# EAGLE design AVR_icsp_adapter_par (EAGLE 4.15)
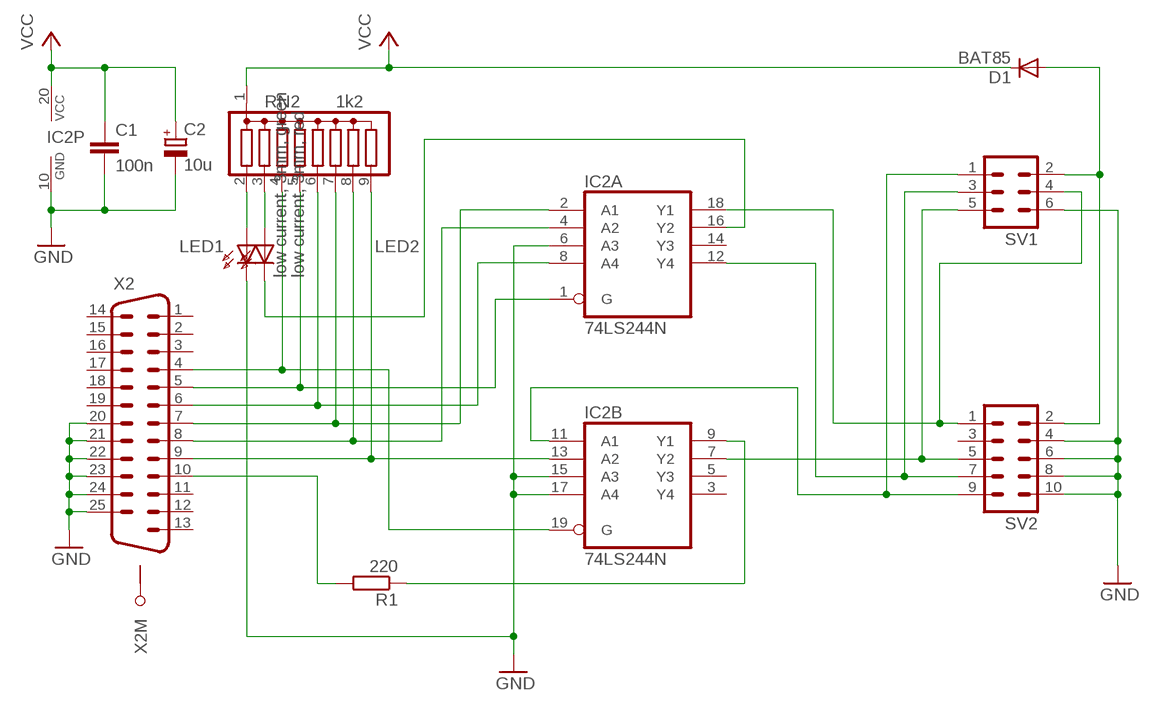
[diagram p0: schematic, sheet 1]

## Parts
C1  100n  C-EU025-025X050  [C025-025X050]
C2  10u  CPOL-EUE2.5-5  [E2,5-5]
D1  BAT85  1N4148  [DO35-10]
IC2  74LS244N  [DIL20]
LED1  low current, 3mm, green  LED3MM  [LED3MM]
LED2  low current, 3mm, red  LED3MM  [LED3MM]
R1  220  R-EU_0309/12  [0309/12]
RN2  1k2  G08R  [SIL9]
SV1  MA03-2  [MA03-2]
SV2  MA05-2  [MA05-2]
X2  M25HP  [M25HP]

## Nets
GND: C1.2 C2.- IC2.6(A:A3) IC2.10(P:GND) IC2.15(B:A3) IC2.17(B:A4) LED1.K(C) SV1.6 SV2.4 SV2.6 SV2.8 SV2.10 X2.20 X2.21 X2.22 X2.23 X2.24 X2.25
N$1: IC2.2(A:A1) RN2.7 X2.7
N$2: IC2.12(A:Y4) SV1.3 SV2.7
N$3: D1.A SV1.2 SV2.2
N$4: IC2.7(B:Y2) SV1.5 SV2.5
N$5: IC2.11(B:A1) SV1.1 SV2.9
N$6: IC2.9(B:Y1) R1.1
N$7: LED2.A RN2.3
N$8: IC2.4(A:A2) RN2.8 X2.8
N$9: IC2.18(A:Y1) SV1.4 SV2.1
N$10: IC2.8(A:A4) RN2.6 X2.6
N$11: IC2.16(A:Y2) LED2.K(C)
N$12: LED1.A RN2.2
N$14: IC2.13(B:A2) RN2.9 X2.9
N$15: IC2.1(A:G) RN2.5 X2.5
N$16: IC2.19(B:G) RN2.4 X2.4
N$17: R1.2 X2.10
VCC: C1.1 C2.+ D1.C IC2.20(P:VCC) RN2.1
Unconnected: IC2.3(B:Y4) IC2.5(B:Y3) IC2.14(A:Y3) SV2.3 X2.1 X2.2 X2.3 X2.11 X2.12 X2.13 X2.14 X2.15 X2.16 X2.17 X2.18 X2.19 X2.G1 X2.G2

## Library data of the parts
C1 = rcl:C-EU: CAPACITOR, European symbol
C2 = rcl:CPOL-EU: POLARIZED CAPACITOR, European symbol
D1 = diode:1N4148: DIODE
IC2 = 74xx-eu:74*244: Octal BUFFER and LINE DRIVER, 3-state
LED1 LED2 = led:LED3MM: LED
R1 = rcl:R-EU_: RESISTOR, European symbol
RN2 = resistor-sil:G08R: SIL RESISTOR
SV1 = con-lstb:MA03-2: PIN HEADER
SV2 = con-lstb:MA05-2: PIN HEADER
X2 = con-subd:M25HP: SUB-D

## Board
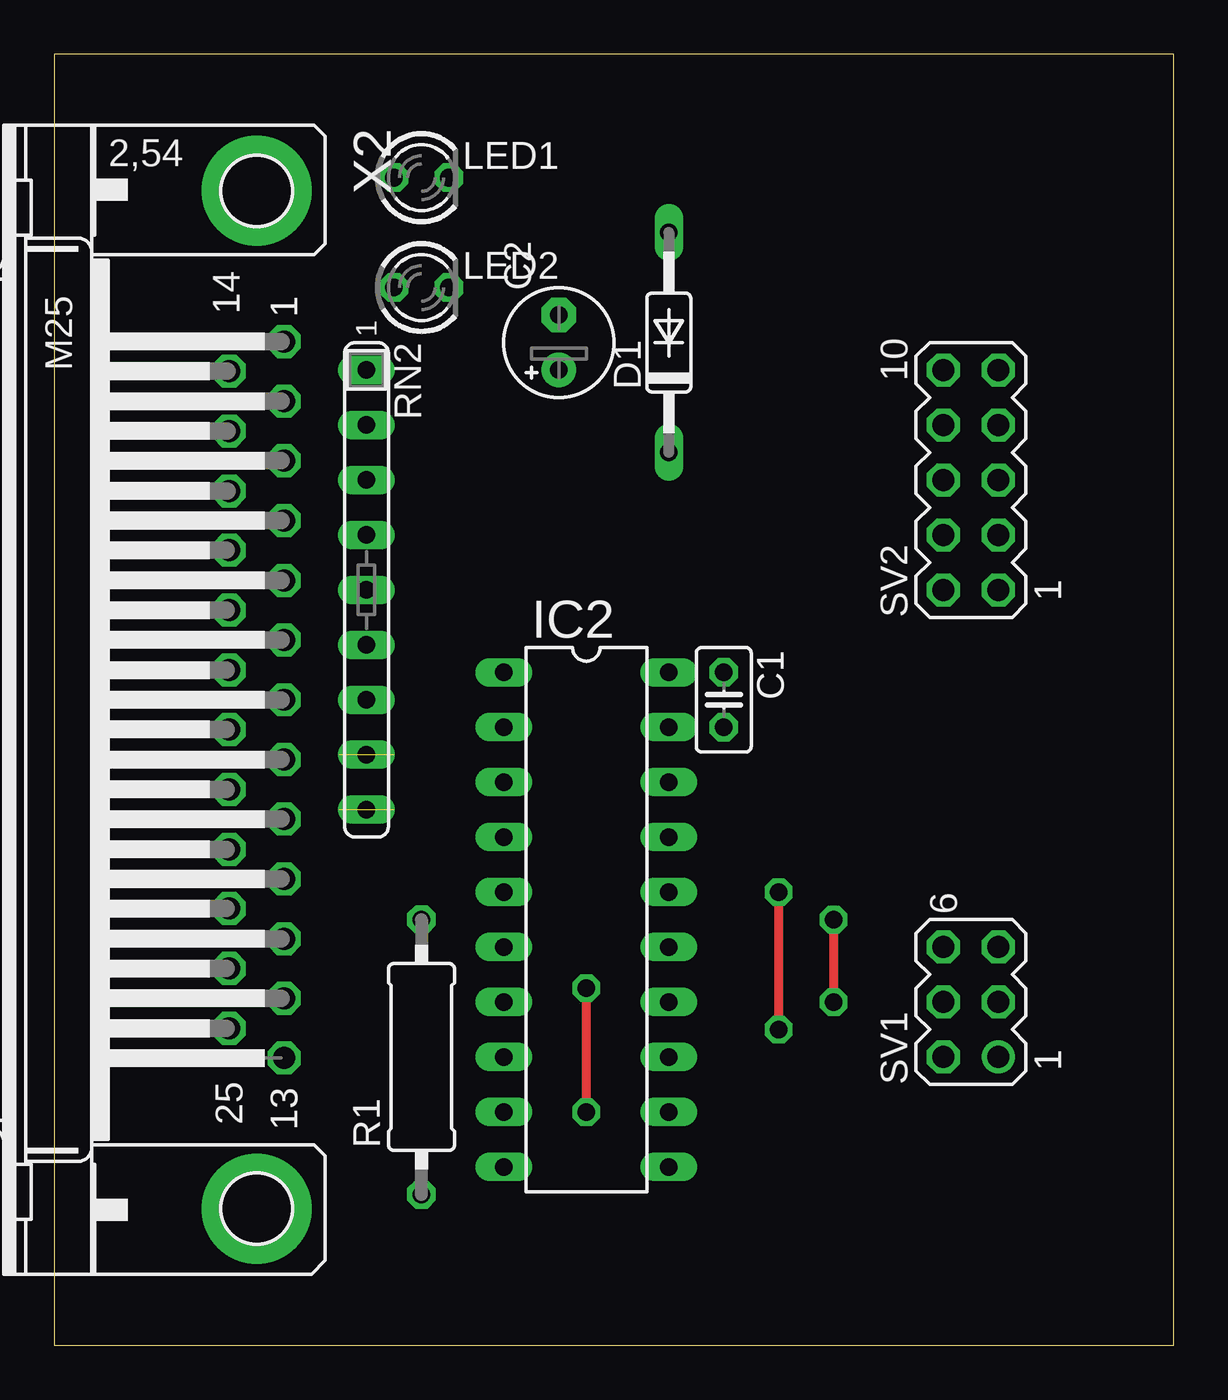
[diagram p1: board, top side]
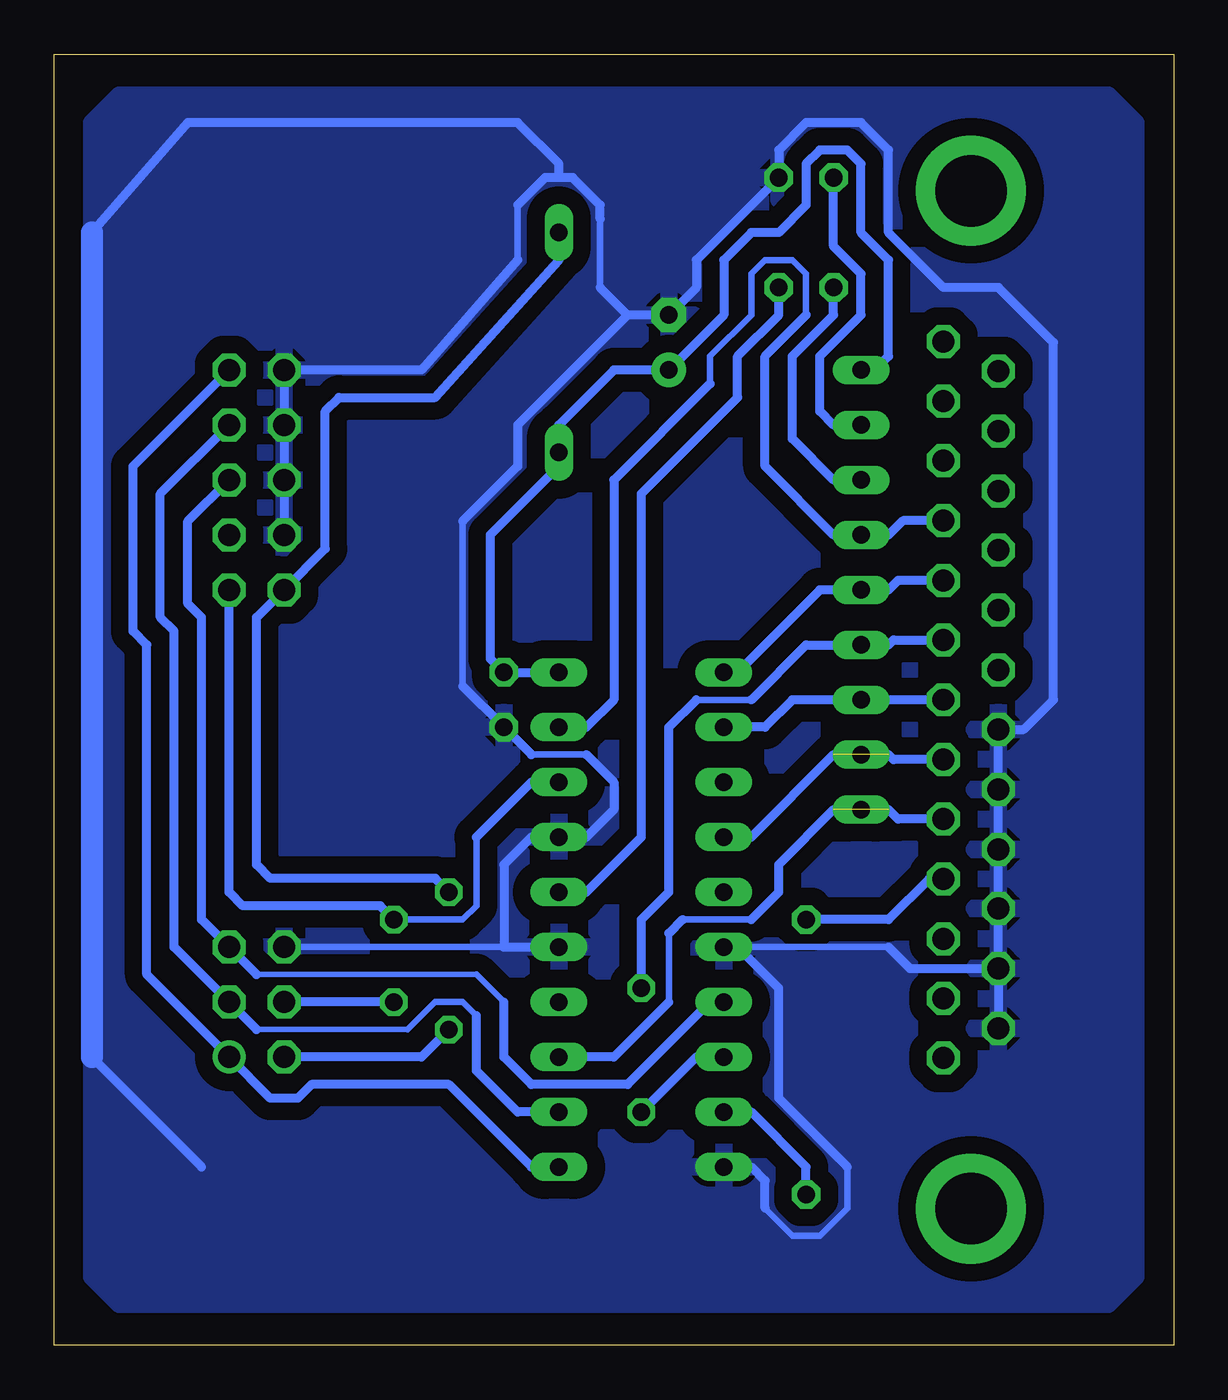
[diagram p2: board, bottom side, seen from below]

Size 51.74 x 59.68 mm. Coordinates in mm from the lower left corner, seen from the top.
Outline: 0,0 51.74,0 51.74,59.68 0,59.68 0,0
Copper layers (1*16): Top 0.035mm / dielectric 1.5mm / Bottom 0.035mm
Design rules "default": minimum track width 10mil, minimum drill 24mil, track to track 8mil, track to pad 8mil, pad to pad 8mil, via to via 8mil, smd to smd 8mil, copper to edge 40mil, drill to drill 8mil, minimum pad ring 10mil, minimum via ring 8mil, stop-mask expansion 4mil, vias tented up to drill 0mil, thermal gap 10mil

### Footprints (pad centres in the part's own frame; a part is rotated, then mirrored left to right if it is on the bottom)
C025-025X050 = drill 0.813 octagon: 1 -1.27,0; 2 1.27,0
E2,5-5 = drill 0.813 pad 1.6 round: + -1.27,0 | drill 0.813 pad 1.6 octagon: - 1.27,0
DO35-10 = drill 0.813 long: A 5.08,0; C -5.08,0
DIL20 = drill 0.813 long: 1 -11.43,-3.81; 2 -8.89,-3.81; 3 -6.35,-3.81; 4 -3.81,-3.81; 5 -1.27,-3.81; 6 1.27,-3.81; 7 3.81,-3.81; 8 6.35,-3.81; 9 8.89,-3.81; 10 11.43,-3.81; 11 11.43,3.81; 12 8.89,3.81; 13 6.35,3.81; 14 3.81,3.81; 15 1.27,3.81; 16 -1.27,3.81; 17 -3.81,3.81; 18 -6.35,3.81; 19 -8.89,3.81; 20 -11.43,3.81
LED3MM = drill 0.813 octagon: A -1.27,0; K 1.27,0
0309/12 = drill 0.813 octagon: 1 -6.35,0; 2 6.35,0
SIL9 = drill 0.813 long: 1 -10.16,0; 2 -7.62,0; 3 -5.08,0; 4 -2.54,0; 5 0,0; 6 2.54,0; 7 5.08,0; 8 7.62,0; 9 10.16,0
MA03-2 = drill 1.016 round: 1 -2.54,-1.27 | drill 1.016 octagon: 2 -2.54,1.27; 3 0,-1.27; 4 0,1.27; 5 2.54,-1.27; 6 2.54,1.27
MA05-2 = drill 1.016 octagon: 1 -5.08,-1.27; 2 -5.08,1.27; 3 -2.54,-1.27; 4 -2.54,1.27; 5 0,-1.27; 6 0,1.27; 7 2.54,-1.27; 8 2.54,1.27; 9 5.08,-1.27; 10 5.08,1.27
M25HP = drill 1.016 octagon: 1 -16.561,1.27; 2 -13.792,1.27; 3 -11.049,1.27; 4 -8.28,1.27; 5 -5.512,1.27; 6 -2.769,1.27; 7 0,1.27; 8 2.769,1.27; 9 5.512,1.27; 10 8.28,1.27; 11 11.049,1.27; 12 13.792,1.27; 13 16.561,1.27; 14 -15.189,-1.27; 15 -12.421,-1.27; 16 -9.652,-1.27; 17 -6.909,-1.27; 18 -4.14,-1.27; 19 -1.372,-1.27; 20 1.372,-1.27; 21 4.14,-1.27; 22 6.909,-1.27; 23 9.652,-1.27; 24 12.421,-1.27; 25 15.189,-1.27 | drill 3.302 pad 5.08 round: G1 -23.52,0; G2 23.52,0

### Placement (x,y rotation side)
C1  30.95,29.84 270 top
C2  23.33,46.35 90 top
D1  28.41,46.35 90 top
IC2  24.6,19.68 270 top
LED1  16.98,53.97 0 top
LED2  16.98,48.89 0 top
R1  16.98,13.33 90 top
RN2  14.44,34.92 270 top
SV1  42.38,15.87 90 top
SV2  42.38,40 90 top
X2  9.36,29.84 270 top

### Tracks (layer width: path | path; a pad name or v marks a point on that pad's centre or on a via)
GND
  Bottom 0.305: 29.68,27.3 27.14,27.3 | 18.88,6.34 17.61,5.08 16.34,5.08 15.08,6.34 15.08,8.25 | 20.15,18.41 13.17,18.41 | 30.95,18.41 SV1.6 | 32.85,38.1 32.85,30.47 | 30.31,52.7 30.31,50.16 | 26.5,48.89 26.5,52.07
  Bottom 0.406: 29.68,27.3 C1.2 32.85,30.47 | 27.14,27.3 25.87,26.03 25.87,24.76 27.14,23.49 IC2.17 29.68,23.49 30.95,22.22 30.95,18.41 IC2.15 | 8.09,26.03 X2.20 6.92,28.47 5.55,29.84 5.55,46.35 8.09,48.89 10.63,48.89 13.17,51.43 13.17,55.24 14.44,56.51 16.98,56.51 18.25,55.24 LED1.K 22.06,50.16 22.06,48.89 C2.- 25.23,47.62 | 8.09,26.03 X2.21 | 8.09,26.03 X2.22 X2.23 | X2.23 8.09,19.68 | X2.24 8.09,17.14 | X2.24 X2.23 | 8.09,14.6 X2.25 X2.24 | IC2.6 20.15,18.41 18.25,16.5 18.25,11.43 15.08,8.25 | IC2.10 19.52,8.25 18.88,7.62 18.88,6.34 | X2.24 12.18,17.42 13.17,18.41 | SV2.4 SV2.6 SV2.8 SV2.10 34.76,45.08 30.31,50.16 | 25.23,47.62 30.31,42.54 30.31,40.64 32.85,38.1 | 28.41,53.97 29.04,53.97 30.31,52.7 | 26.5,52.07 26.5,52.7 27.77,53.97 28.41,53.97 | 25.23,47.62 26.5,48.89 | 28.41,53.97 28.41,54.61 30.31,56.51 45.55,56.51 50,51.43 | 50,13.33 44.92,8.25
  Bottom 1.016: 50,51.43 50,13.33
  pour Bottom (isolate 0.813): 1.74,56.51 3.01,57.78 48.73,57.78 50,56.51 50,3.17 48.73,1.9 3.01,1.9 1.74,3.17
N$1
  Bottom 0.406: IC2.2 18.88,28.57 17.61,29.84 RN2.7 X2.7
N$2
  Bottom 0.254: 35.39,14.6 42.38,14.6
  Bottom 0.305: 35.39,14.6 34.12,15.87 32.85,15.87 32.22,15.24
  Bottom 0.406: 42.38,14.6 SV1.3 46.19,18.41 46.19,33.02 46.82,33.65 46.82,39.37 SV2.7 | 32.22,15.24 32.22,12.7 30.31,10.79 IC2.12
N$3  (via drill 0.81 pad 1.27)
  Top 0.406: v33.49,14.6 v33.49,20.95
  Bottom 0.406: v33.49,20.95 34.12,21.58 41.74,21.58 42.38,22.22 42.38,33.65 SV2.2 39.2,36.83 39.2,43.18 38.57,43.81 34.12,43.81 28.41,50.16 D1.A | v33.49,14.6 34.76,13.33 SV1.2
N$4
  Bottom 0.254: 32.22,17.14 42.38,17.14
  Bottom 0.305: 30.95,15.87 32.22,17.14
  Bottom 0.406: IC2.7 21.42,15.87 25.23,12.06 29.68,12.06 30.95,13.33 30.95,15.87 | 42.38,17.14 SV1.5 44.92,19.68 44.92,33.65 45.55,34.29 45.55,38.1 SV2.5
N$5
  Bottom 0.406: IC2.11 29.68,8.25 33.49,12.06 39.84,12.06 40.48,11.43 41.74,11.43 SV1.1 47.46,17.14 47.46,32.38 48.09,33.02 48.09,40.64 SV2.9
N$6
  Bottom 0.406: R1.1 16.98,8.25 19.52,10.79 IC2.9
N$7
  Bottom 0.406: LED2.A 15.71,47.62 17.61,45.72 17.61,41.91 15.71,40 RN2.3
N$8  (2 unrouted)
  Bottom 0.406: 15.71,27.3 19.52,23.49 IC2.4 | X2.8 12.94,27.07 13.17,27.3
N$9  (via drill 0.81 pad 1.27)
  Top 0.406: v36.03,19.68 v36.03,15.87
  Bottom 0.305: v36.03,19.68 32.85,19.68 32.22,20.31 32.22,23.49
  Bottom 0.406: v36.03,15.87 SV1.4 | 32.22,23.49 29.68,26.03 IC2.18 | v36.03,19.68 36.66,20.31 43.02,20.31 43.65,20.95 SV2.1
N$10  (via drill 0.81 pad 1.27)
  Top 0.406: v24.6,10.79 v24.6,16.5
  Bottom 0.305: 22.06,29.84 19.52,29.84
  Bottom 0.406: X2.6 12.94,32.61 13.17,32.38 RN2.6 16.98,32.38 19.52,29.84 | 22.06,29.84 23.33,28.57 23.33,20.95 24.6,19.68 v24.6,16.5 | IC2.8 22.06,13.33 v24.6,10.79
N$11
  Bottom 0.406: IC2.16 27.14,20.95 24.6,23.49 24.6,39.37 20.15,43.81 20.15,45.72 18.25,47.62 LED2.K
N$12
  Bottom 0.406: RN2.2 15.71,42.54 16.34,43.18 16.34,45.72 14.44,47.62 14.44,49.53 15.71,50.8 LED1.A
N$14  (2 unrouted)
  Bottom 0.305: 19.52,19.68 22.7,19.68 | 23.33,19.04 23.33,15.87
  Bottom 0.406: X2.9 12.74,24.33 13.17,24.76 | 15.71,24.76 18.25,22.22 18.25,20.95 19.52,19.68 | 22.7,19.68 23.33,19.04 | 23.33,15.87 25.87,13.33 IC2.13
N$15
  Bottom 0.406: IC2.1 20.15,31.11 16.34,34.92 RN2.5 13.17,34.92 12.74,35.35 X2.5
N$16
  Bottom 0.305: 16.98,47.62 16.98,49.53 17.61,50.16 18.88,50.16 19.52,49.53 19.52,47.62 21.42,45.72 21.42,44.45
  Bottom 0.406: X2.4 12.51,38.12 13.17,37.46 RN2.4 15.71,37.46 18.88,40.64 18.88,45.72 16.98,47.62 | IC2.19 27.14,28.57 25.87,29.84 25.87,40 21.42,44.45
N$17
  Bottom 0.406: X2.10 11.29,21.56 13.17,19.68 R1.2
VCC
  Bottom 0.406: IC2.20 C1.1 31.58,31.74 31.58,37.46 28.41,40.64 D1.C 28.41,42.54 25.87,45.08 C2.+ 20.79,47.62 20.79,50.16 19.52,51.43 18.25,51.43 16.98,52.7 16.98,54.61 16.34,55.24 15.08,55.24 14.44,54.61 14.44,51.43 13.17,50.16 13.17,45.72 13.81,45.08 RN2.1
